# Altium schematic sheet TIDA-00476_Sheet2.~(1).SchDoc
size 431 x 279 mm; Date: Not shown in title block; ApprovedBy: Not shown in title block; CheckedBy: Not shown in title block; Author: Not shown in title block; CompanyName: Not shown in title block; DrawnBy: Salil Chellappan; Engineer: Not shown in title block; Organization: Not shown in title block; Address1: Not shown in title block; Address2: Not shown in title block; Address3: Not shown in title block; Address4: Not shown in title block; DocumentNumber: 2; Revision: Use project parameter SCH_Rev; SheetNumber: 2; SheetTotal: 3; PageSetup: Record=PageOptions¦CenterHorizontal=True¦CenterVertical=True¦PrintScale=0.64¦XCorrection=1.00¦YCorrection=1.00¦PrintKind=0¦BorderSize=5000000¦LeftOffset=0¦BottomOffset=0¦Orientation=2¦PaperLength=1000¦PaperWidth=1000¦Scale=100¦PaperSource=15¦PrintQuality=600¦MediaType=1¦DitherType=10¦PrintScaleMode=1¦PaperKind=Letter
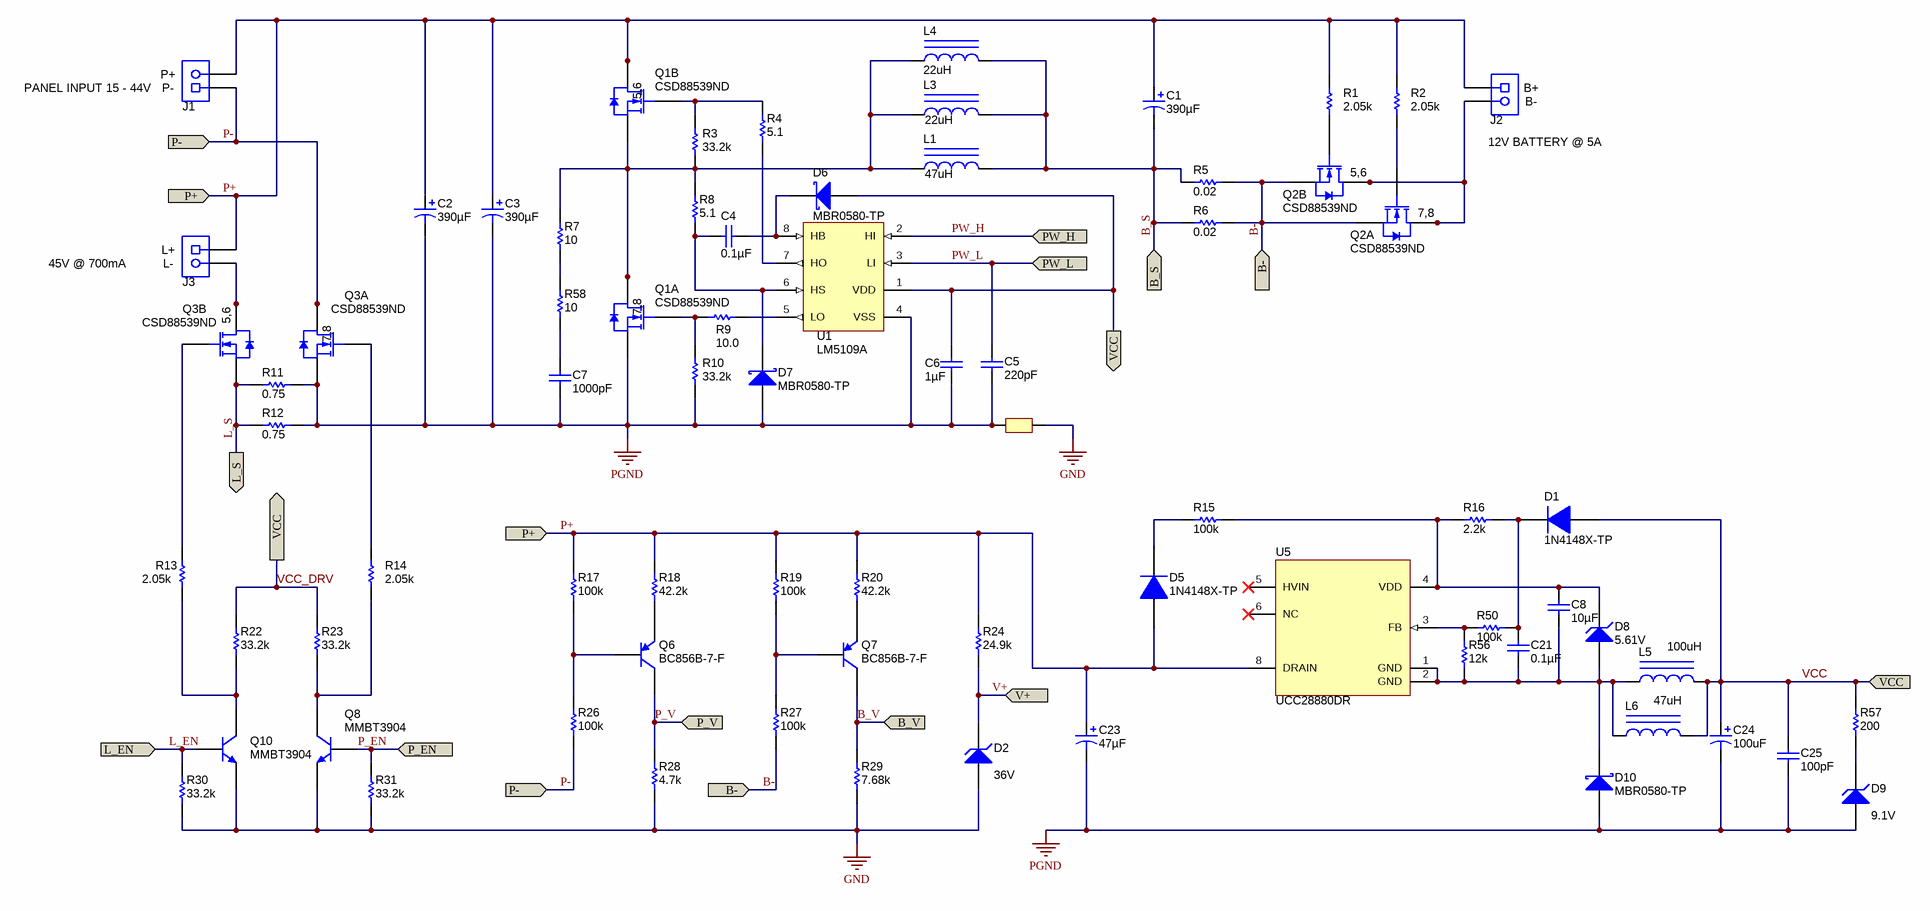
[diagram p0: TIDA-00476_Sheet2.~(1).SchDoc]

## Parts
C1  ValueDisplayed: 390µF  [KZN_1000x2000]  (hidden comment: EKYB630ELL391MJ30S)
C2  ValueDisplayed: 390µF  [KZN_1000x2000]  (hidden comment: EKYB630ELL391MJ30S)
C3  ValueDisplayed: 390µF  [KZN_1000x2000]  (hidden comment: EKYB630ELL391MJ30S)
C4  ValueDisplayed: 0.1µF  [0805_HV]  (hidden comment: 08053C104KAT2A)
C5  ValueDisplayed: 220pF  [0805_HV]  (hidden comment: GRM2165C2A221JA01D)
C6  ValueDisplayed: 1µF  [0805_HV]  (hidden comment: 08055C105KAT2A)
C7  ValueDisplayed: 1000pF  [0805_HV]  (hidden comment: GRM2195C2A102JA01D)
C8  ValueDisplayed: 10µF  [0603]  (hidden comment: C1608X5R1A106M)
C21  ValueDisplayed: 0.1µF  [0603]  (hidden comment: 0603YC104JAT2A)
C23  ValueDisplayed: 47µF  [ZLJ_500x1100]  (hidden comment: 35ZLJ47MTA5X11)
C24  ValueDisplayed: 100uF  [ZLJ_500x1100]  (hidden comment: 16PX100MEFCTA5X11)
C25  ValueDisplayed: 100pF  [0603]  (hidden comment: 06033C101KAT2A)
D1  1N4148X-TP  [SOD-523]
D2  value 36V  [SOD-123]  (hidden comment: MMSZ4715-V)
D5  1N4148X-TP  [SOD-523]
D6  MBR0580-TP  [SOD-123]
D7  MBR0580-TP  [SOD-123]
D8  5.61V  [SOD-523]
D9  value 9.1V  [SOD-123]  (hidden comment: MMSZ4696-V)
D10  MBR0580-TP  [SOD-123]
J1  282841-2  [TEC_282841-2]  (value not drawn)
J2  282841-2  [TEC_282841-2]  (value not drawn)
J3  282841-2  [TEC_282841-2]  (value not drawn)
L1  value 47uH  [WE-HCB_1890]  (hidden comment: 74435574700)
L3  value 22uH  [mss1278]  (hidden comment: MSS1278-223MLB)
L4  22uH  [WE-HCB_1890]
L5  100uH  [SRN3015]
L6  47uH  [SRN3015]
NT1  Net-Tie  [Net-Tie_20milWide_60milLong]  (value not drawn)  (net tie, no BOM)
Q1  CSD88539ND  [SO-8L]  (parts A,B of 2)
Q2  CSD88539ND  [SO-8L]  (parts A,B of 2)
Q3  CSD88539ND  [SO-8L]  (parts A,B of 2)
Q6  BC856B-7-F  [SOT-23]
Q7  BC856B-7-F  [SOT-23]
Q8  MMBT3904  [SOT-23L]
Q10  MMBT3904  [SOT-23L]
R1  value 2.05k  [0805_HV]  (hidden comment: CRCW08052K05FKEA)
R2  value 2.05k  [0805_HV]  (hidden comment: CRCW08052K05FKEA)
R3  value 33.2k  [0805_HV]  (hidden comment: CRCW080533K2FKEA)
R4  ValueDisplayed: 5.1  [0805_HV]  (hidden comment: RC0805JR-075R1L)
R5  ValueDisplayed: 0.02  [1206]  (hidden comment: CSR1206FK20L0)
R6  ValueDisplayed: 0.02  [1206]  (hidden comment: CSR1206FK20L0)
R7  ValueDisplayed: 10  [1206]  (hidden comment: CRCW120610R0JNEA)
R8  ValueDisplayed: 5.1  [0603]  (hidden comment: CRCW06035R10JNEA)
R9  value 10.0  [0805_HV]  (hidden comment: CRCW080510R0FKEA)
R10  value 33.2k  [0805_HV]  (hidden comment: CRCW080533K2FKEA)
R11  ValueDisplayed: 0.75  [1206]  (hidden comment: CSR1206FKR750)
R12  ValueDisplayed: 0.75  [1206]  (hidden comment: CSR1206FKR750)
R13  value 2.05k  [0805_HV]  (hidden comment: CRCW08052K05FKEA)
R14  value 2.05k  [0805_HV]  (hidden comment: CRCW08052K05FKEA)
R15  ValueDisplayed: 100k  [0603]  (hidden comment: CRCW0603100KJNEA)
R16  ValueDisplayed: 2.2k  [0603]  (hidden comment: CRCW06032K20JNEA)
R17  value 100k  [0805_HV]  (hidden comment: CRCW0805100KFKEA)
R18  ValueDisplayed: 42.2k  [0805_HV]  (hidden comment: CRCW080542K2FKEA)
R19  value 100k  [0805_HV]  (hidden comment: CRCW0805100KFKEA)
R20  ValueDisplayed: 42.2k  [0805_HV]  (hidden comment: CRCW080542K2FKEA)
R22  value 33.2k  [0805_HV]  (hidden comment: CRCW080533K2FKEA)
R23  value 33.2k  [0805_HV]  (hidden comment: CRCW080533K2FKEA)
R24  ValueDisplayed: 24.9k  [0805_HV]  (hidden comment: ERJ-6ENF2492V)
R26  value 100k  [0805_HV]  (hidden comment: CRCW0805100KFKEA)
R27  value 100k  [0805_HV]  (hidden comment: CRCW0805100KFKEA)
R28  ValueDisplayed: 4.7k  [0805_HV]  (hidden comment: CRCW08054K70JNEA)
R29  ValueDisplayed: 7.68k  [0805_HV]  (hidden comment: CRCW08057K68FKEA)
R30  value 33.2k  [0805_HV]  (hidden comment: CRCW080533K2FKEA)
R31  value 33.2k  [0805_HV]  (hidden comment: CRCW080533K2FKEA)
R50  ValueDisplayed: 100k  [0603]  (hidden comment: CRCW0603100KJNEA)
R56  ValueDisplayed: 12k  [0603]  (hidden comment: CRCW060312K0JNEA)
R57  ValueDisplayed: 200  [0603]  (hidden comment: CRCW0603200RJNEA)
R58  ValueDisplayed: 10  [1206]  (hidden comment: CRCW120610R0JNEA)
U1  LM5109A  [M08A_N]
U5  UCC28880DR  [D0007A_N]

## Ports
B- (in), B_S (in), B_V (in), L_EN (in), L_S (out), P+ (in), P- (in), P_EN (in), P_V (in), PW_H, PW_L, V+, VCC

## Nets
GND: D2.2(A) NT1.1 Q8.2(E) Q10.2(E) R28.1 R29.1 R30.1 R31.1
PGND: C2.2(-) C3.2(-) C5.2 C6.2 C7.2 C23.2(-) C24.2(-) C25.2 D7.2(A) D9.2(A) D10.2(A) NT1.2 Q1.1(S) Q3.1(S) R10.1 R11.2 R12.2 U1.4(VSS)
B-: Q2.1(S) Q2.3(S) R5.2 R6.2 R27.1 ; port B-
B_S: C1.2(-) L1.2 L3.2 L4.2 R5.1 R6.1 ; port B_S
B_V: Q7.3(C) R29.2 ; port B_V
L_EN: Q10.1(B) R30.2 ; port L_EN
L_S: Q3.3(S) R11.1 R12.1 ; port L_S
P+: C1.1(+) C2.1(+) C3.1(+) C23.1(+) D5.2(A) J1.2 J2.1 J3.1 Q1.5(D) Q1.6(D) R1.2 R2.2 R17.2 R18.2 R19.2 R20.2 R24.2 U5.8(DRAIN) ; port P+
P-: J1.1 Q3.7(D) Q3.8(D) R26.1 ; port P-
P_EN: Q8.1(B) R31.2 ; port P_EN
P_V: Q6.3(C) R28.2 ; port P_V
PW_H: U1.2(HI) ; port PW_H
PW_L: C5.1 U1.3(LI) ; port PW_L
V+: D2.1(K) R24.1 ; port V+
VCC: C6.1 C24.1(+) C25.1 D1.2(A) D6.2(A) L5.2 L6.2 R22.2 R23.2 R57.2 U1.1(VDD) ; port VCC  [also labelled VCC_DRV]
NetC4_1: C4.1 D6.1(K) U1.8(HB)
NetC4_2: C4.2 D7.1(K) R8.1 U1.6(HS)
NetC7_1: C7.1 R58.1
NetC8_1: C8.1 D8.1(K) R15.1 R16.1 U5.4(VDD)
NetC8_2: C8.2 C21.2 D8.2(A) D10.1(K) L5.1 L6.1 R56.1 U5.1(GND) U5.2(GND)
NetC21_1: C21.1 D1.1(K) R16.2 R50.1
NetD5_1: D5.1(K) R15.2
NetD9_1: D9.1(K) R57.1
NetJ2_2: J2.2 Q2.5(D) Q2.6(D) Q2.7(D) Q2.8(D)
NetJ3_2: J3.2 Q3.5(D) Q3.6(D)
NetL1_1: L1.1 L3.1 L4.1 Q1.3(S) Q1.7(D) Q1.8(D) R3.1 R7.2 R8.2
NetQ1_2: Q1.2(G) R9.1 R10.2
NetQ1_4: Q1.4(G) R3.2 R4.2
NetQ2_2: Q2.2(G) R2.1
NetQ2_4: Q2.4(G) R1.1
NetQ3_2: Q3.2(G) R14.2
NetQ3_4: Q3.4(G) R13.2
NetQ6_1: Q6.1(B) R17.1 R26.2
NetQ6_2: Q6.2(E) R18.1
NetQ7_1: Q7.1(B) R19.1 R27.2
NetQ7_2: Q7.2(E) R20.1
NetQ8_3: Q8.3(C) R14.1 R23.1
NetQ10_3: Q10.3(C) R13.1 R22.1
NetR4_1: R4.1 U1.7(HO)
NetR7_1: R7.1 R58.2
NetR9_2: R9.2 U1.5(LO)
NetR50_2: R50.2 R56.2 U5.3(FB)

Not connected (* = marked no-connect by the designer): U5 5(HVIN)* 6(NC)*

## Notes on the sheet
- PANEL INPUT 15 - 44V
- (near J1) P+
- (near J1) P-
- (near J2) B-
- (near J2) B+
- (near J2) 12V BATTERY @ 5A
- 45V @ 700mA
- (near J3) L-
- (near J3) L+

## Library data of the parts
C1 = EKZN350ELL471MJ20S: CAP, AL,390 µF, 63 V, +/- 20%, 0.043 ohm, TH; Manufacturer: Chemi-Con; Polarized: Y; CompType: Capacitor; Value: 390uF; U/M: EA; Cap_F: 0.00039; Tolerance_%: 20; Value1: 0.04 ohm; VDC_V: 63; Value2: 63V; ESR_ohm: 0.04; IRMS_A: 1.78; TaMin_C: -40; TaMax_C: 105; Cap_Case: 10x30mm
C2 C3 = EKZN350ELL471MJ20S: CAP, AL, 470 µF, 35 V, +/- 20%, 0.028 ohm, TH; Manufacturer: Chemi-Con; Polarized: Y; CompType: Capacitor; Value: 390uF; U/M: EA; Cap_F: 0.00039; Tolerance_%: 20; Value1: 0.04 ohm; VDC_V: 63; Value2: 63V; ESR_ohm: 0.04; IRMS_A: 1.78; TaMin_C: -40; TaMax_C: 105; Cap_Case: 10x30mm
C4 = 08053C104KAT2A: CAP, CERM, 0.1uF, 25V, +/-10%, X7R, 0805; Manufacturer: AVX; Polarized: N; CompType: Capacitor; U/M: EA; Cap_F: 0.0000001; Tolerance_%: 10; ESR_Ohm: 0.28; Value1: 0.28 ohm; VDC_V: 25; TaMin_C: -55; TaMax_C: 125; Cap_Case: 0805
C5 = GRM2165C2A221JA01D: CAP, CERM, 220 pF, 100 V, +/- 5%, C0G/NP0, 0805; Manufacturer: MuRata; Polarized: N; CompType: Capacitor; Value: 220pF; U/M: EA; Cap_F: 0.00000000022; Tolerance_%: 5; Value1: Unknown; VDC_V: 100; Value2: 100V; TaMin_C: -55; TaMax_C: 125; Cap_Case: 0805
C6 = 08055C105KAT2A: CAP, CERM, 1uF, 50V, +/-10%, X7R, 0805; Manufacturer: AVX; Polarized: N; CompType: Capacitor; U/M: EA; Cap_F: 0.000001; Tolerance_%: 10; Value1: Unknown; VDC_V: 50; TaMin_C: -55; TaMax_C: 125; Cap_Case: 0805
C7 = GRM2195C2A102JA01D: CAP, CERM, 1000 pF, 100 V, +/- 5%, C0G/NP0, 0805; Manufacturer: MuRata; Polarized: N; CompType: Capacitor; Value: 1000pF; U/M: EA; Cap_F: 0.000000001; Tolerance_%: 5; Value1: Unknown; VDC_V: 100; Value2: 100V; TaMin_C: -55; TaMax_C: 125; Cap_Case: 0805
C8 = C1608X5R1A106M: CAP, CERM, 10 µF, 10 V, +/- 20%, X5R, 0603; Manufacturer: TDK; Polarized: N; CompType: Capacitor; Value: 10uF; U/M: EA; Cap_F: 0.00001; Tolerance_%: 20; ESR_ohm: 0.0078; Value1: 0.0078 ohm; VDC_V: 10; Value2: 10V; IRMS_A: 1.85; TaMin_C: -55; TaMax_C: 85
C21 = 0603YC104JAT2A: CAP, CERM, 0.1 µF, 16 V, +/- 5%, X7R, 0603; Manufacturer: AVX; Polarized: N; CompType: Capacitor; Value: 0.1uF; U/M: EA; Cap_F: 0.0000001; Tolerance_%: 5; ESR_ohm: 0.039; Value1: 0.039 ohm; VDC_V: 16; Value2: 16V; TaMin_C: -55; TaMax_C: 125
C23 = 35ZLJ47MTA5X11: CAP, AL, 47 µF, 35 V, +/- 20%, 0.4 ohm, TH; Manufacturer: Rubycon; Polarized: Y; CompType: Capacitor; Value: 47uF; U/M: EA; Cap_F: 0.000047; Tolerance_%: 20; Value1: 0.4 ohm; VDC_V: 35; Value2: 35V; ESR_ohm: 0.4; IRMS_A: 0.45; TaMin_C: -40; TaMax_C: 105; Cap_Case: 5x11mm
C24 = 35ZLJ47MTA5X11: CAP, AL, 100 µF, 16 V, +/- 20%, 0.4 ohm, TH; Manufacturer: Rubycon; Polarized: Y; CompType: Capacitor; Value: 100uF; U/M: EA; Cap_F: 0.000047; Tolerance_%: 20; Value1: 0.4 ohm; VDC_V: 16; Value2: 16V; ESR_ohm: 0.4; IRMS_A: 0.45; TaMin_C: -40; TaMax_C: 105; Cap_Case: 5x11mm
C25 = 06033C101KAT2A: CAP, CERM, 100 pF, 25 V, +/- 10%, X7R, 0603; Manufacturer: AVX; Polarized: N; CompType: Capacitor; Value: 100pF; U/M: EA; Cap_F: 0.0000000001; Tolerance_%: 10; Value1: Unknown; VDC_V: 25; Value2: 25V; TaMin_C: -55; TaMax_C: 125
D1 D5 = 1N4148X-TP: Diode, Switching, 75 V, 0.3 A, SOD-523; Manufacturer: Micro Commercial Components; U/M: EA; Vf_V: 1.25; Value: 75V; Value1: 0.3A; Value2: 1.25V; Io_A: 0.3; Vr_V: 75; TJmax_C: 150
D2 = MMSZ4715-V: Diode, Zener, 36 V, 500 mW, SOD-123; Manufacturer: Vishay-Semiconductor; SymbolCreator: a0412235; U/M: EA; Power_W: 0.5; Vz_V: 36; Value1: 0.5W; RJA_CperW: 67
D6 D7 D10 = MBR0580-TP: Diode, Schottky, 80 V, 0.5 A, SOD-123; Manufacturer: Micro Commercial Components; U/M: EA; Vf_V: 0.8; Value: 80V; Value1: 0.5A; Value2: 0.8V; Io_A: 0.5; Vr_V: 80; TJmax_C: 150
D8 = MM5Z5V6ST1G: Diode, Zener, 5.61 V, 500 mW, SOD-523; Manufacturer: ON Semiconductor; SymbolCreator: a0412235; U/M: EA; Power_W: 0.5; Vz_V: 5.61; Value1: 0.5W; RJA_CperW: 250
D9 = MMSZ4696-V: Diode, Zener, 9.1 V, 500 mW, SOD-123; Manufacturer: Vishay-Semiconductor; SymbolCreator: a0412235; U/M: EA; Power_W: 0.5; Vz_V: 9.1; Value1: 0.5W; RJA_CperW: 67
J1-J3 = 282841-2: Terminal Block, 2x1, 5.08mm, TH; Manufacturer: TE Connectivity; SymbolCreator: a0412235; U/M: EA
L1 = 74435574700: Inductor, Shielded Drum Core, Ferrite, 47 µH, 6.8 A, 0.0335 ohm, SMD; Manufacturer: Wurth Elektronik; Ind_H: 47.0E-6; ValueDisplayed: 47µH; Imax_A: 6.8; Irms: 6.8A @ 50C rise; Isat: 7A @ 30% inductance drop; DCR_ohm: 0.0335; Value2: 6.8A
L3 = MSS1278-223MLB: Inductor, Shielded Drum Core, Ferrite, 22 µH, 4 A, 0.04 ohm, SMD; Manufacturer: Coilcraft; Ind_H: 22.0E-6; ValueDisplayed: 22µH; Imax_A: 4; Irms: 4A @ 40C rise; Isat: 7.24A @ 30% inductance drop; DCR_ohm: 0.04; Value2: 4A
L4 = 74435572200: Inductor, Shielded Drum Core, Ferrite, 22 µH, 11 A, 0.0146 ohm, SMD; Manufacturer: Wurth Elektronik; Ind_H: 22.0E-6; ValueDisplayed: 22µH; Imax_A: 11; Irms: 11A @ 50C rise; Isat: 11A @ 30% inductance drop; DCR_ohm: 0.0146; Value2: 11A
L5 = SRN3015-1R0Y: Inductor, Drum Core, Ferrite, 100 µH, 0.4 A, 1.596 ohm, SMD; PartNumber: SRN4018-101M; Manufacturer: Bourns; Ind_H: 1.0E-4; ValueDisplayed: 100µH; Imax_A: 0.4; DCR_ohm: 0.048; Value2: 0.4A
L6 = SRN3015-1R0Y: Inductor, Drum Core, Ferrite, 47 µH, 0.4 A, 1.4 ohm, SMD; PartNumber: SRN3015-470M; Manufacturer: Bourns; Ind_H: 47E-6; Imax_A: 2.35; DCR_ohm: 0.048; Value1: 1.4Ohm; Value2: 0.4A
NT1 = Net-Tie: Single point connection between nets.; SymbolCreator: codlsc
Q1-Q3 = CSD88539ND: MOSFET, N-CH, 60V, 6.3A, SO-8; Manufacturer: Texas Instruments; Alternate Manufacturer: None; U/M: EA; ChType: N; VdsMax_V: 60; Value1: ? ohm; Value2: 7.2 nC; QgTyp_nC: 7.2; Vgs_V: 20; IdsMax_A: 6.3
Q6 Q7 = BC856B-7-F, Diodes Inc.: Transistor, PNP, 65 V, 0.1 A, SOT-23; CompType: BJT; PNP: 1; NPN: 0; Vceo_V: 65; Vcesat1_V: 0.075; Value: 65 V; IcRated_A: 0.1; Value1: 0.1 A; HfeMax: 330; TaMin_C: -65; TaMax_C: 150; U/M: EA
Q8 Q10 = MMBT3904, Fairchild Semiconductor: Transistor, NPN, 40V, 0.2A, SOT-23; CompType: BJT; PNP: 0; NPN: 1; Vceo_V: 40; Vcesat1_V: 0.2; Value: 0.2V; HfeMax: 300; TaMin_C: -55; TaMax_C: 150; U/M: EA
R1 R2 R13 R14 = CRCW08052K05FKEA: RES, 2.05k ohm, 1%, 0.125W, 0805; Manufacturer: Vishay-Dale; CompType: Resistor; Res_ohm: 2050; Value_Code: 2k05; Tolerance_%: 1; Power_W: 0.125; VDC_V: 150; TempCo: 100 ppm/C; EIA_Code: E96; U/M: EA
R3 R10 R22 R23 R30 R31 = CRCW080533K2FKEA: RES, 33.2k ohm, 1%, 0.125W, 0805; Manufacturer: Vishay-Dale; CompType: Resistor; Res_ohm: 33200; Value_Code: 33k2; Tolerance_%: 1; Power_W: 0.125; VDC_V: 150; TempCo: 100 ppm/C; EIA_Code: E96; U/M: EA
R4 = RC0805JR-075R1L: RES, 5.1, 5%, 0.125 W, 0805; Manufacturer: Yageo America; CompType: Resistor; Value: 5.1; Value_Code: 5R10; Tolerance_%: 5; Power_W: 0.125; Value2: 0.125W; VDC_V: 150; TempCo: 200 ppm/C; EIA_Code: E24; U/M: EA
R5 R6 = CSR1206FK20L0: RES, 0.02, 1%, 0.5 W, 1206; Manufacturer: Stackpole Electronics Inc; CompType: Resistor; Value: 0.02; Value_Code: R020; Tolerance_%: 1; Power_W: 0.5; Value2: 0.5W; TempCo: 100 ppm/C; EIA_Code: E96; U/M: EA
R7 R58 = CRCW120610R0JNEA: RES, 10, 5%, 0.25 W, 1206; Manufacturer: Vishay-Dale; CompType: Resistor; Value: 10; Value_Code: 10R0; Tolerance_%: 5; Power_W: 0.25; Value2: 0.25W; VDC_V: 200; TempCo: 200 ppm/C; EIA_Code: E24; U/M: EA
R8 = CRCW06035R10JNEA: RES, 5.1, 5%, 0.1 W, 0603; Manufacturer: Vishay-Dale; CompType: Resistor; Value: 5.1; Value_Code: 5R10; Tolerance_%: 5; Power_W: 0.1; Value2: 0.1W; VDC_V: 75; TempCo: 200 ppm/C; EIA_Code: E24; U/M: EA
R9 = CRCW080510R0FKEA: RES, 10.0 ohm, 1%, 0.125W, 0805; Manufacturer: Vishay-Dale; CompType: Resistor; Res_ohm: 10; Value_Code: 10R0; Tolerance_%: 1; Power_W: 0.125; VDC_V: 150; TempCo: 100 ppm/C; EIA_Code: E96; U/M: EA
R11 R12 = CSR1206FKR750: RES, 0.75, 1%, 0.5 W, 1206; Manufacturer: Stackpole Electronics Inc; CompType: Resistor; Value: 0.75; Value_Code: R750; Tolerance_%: 1; Power_W: 0.5; Value2: 0.5W; TempCo: 100 ppm/C; EIA_Code: E96; U/M: EA
R15 R50 = CRCW0603100KJNEA: RES, 100 k, 5%, 0.1 W, 0603; Manufacturer: Vishay-Dale; CompType: Resistor; Value: 100k; Res_ohm: 100000; Tolerance_%: 5; Power_W: 0.1; Value2: 0.1W; VDC_V: 75; TempCo: 200 ppm/C; EIA_Code: E24; U/M: EA
R16 = CRCW06032K20JNEA: RES, 2.2 k, 5%, 0.1 W, 0603; Manufacturer: Vishay-Dale; CompType: Resistor; Value: 2.2k; Res_ohm: 2200; Value_Code: 2k20; Tolerance_%: 5; Power_W: 0.1; Value2: 0.1W; VDC_V: 75; TempCo: 200 ppm/C; EIA_Code: E24; U/M: EA
R17 R19 R26 R27 = CRCW0805100KFKEA: RES, 100k ohm, 1%, 0.125W, 0805; Manufacturer: Vishay-Dale; CompType: Resistor; Res_ohm: 100000; Tolerance_%: 1; Power_W: 0.125; VDC_V: 150; TempCo: 100 ppm/C; EIA_Code: E96; U/M: EA
R18 R20 = CRCW080542K2FKEA: RES, 42.2 k, 1%, 0.125 W, 0805; Manufacturer: Vishay-Dale; CompType: Resistor; Value: 42.2k; Res_ohm: 42200; Value_Code: 42k2; Tolerance_%: 1; Power_W: 0.125; Value2: 0.125W; VDC_V: 150; TempCo: 100 ppm/C; EIA_Code: E96; U/M: EA
R24 = ERJ-6ENF2492V: RES, 24.9 k, 1%, 0.125 W, 0805; Manufacturer: Panasonic; CompType: Resistor; Value: 24.9k; Res_ohm: 24900; Value_Code: 24k9; Tolerance_%: 1; Power_W: 0.125; Value2: 0.125W; TempCo: 100 ppm/C; EIA_Code: E96; U/M: EA
R28 = CRCW08054K70JNEA: RES, 4.7 k, 5%, 0.125 W, 0805; Manufacturer: Vishay-Dale; CompType: Resistor; Value: 4.7k; Res_ohm: 4700; Value_Code: 4k70; Tolerance_%: 5; Power_W: 0.125; Value2: 0.125W; VDC_V: 150; TempCo: 200 ppm/C; EIA_Code: E24; U/M: EA
R29 = CRCW08057K68FKEA: RES, 7.68 k, 1%, 0.125 W, 0805; Manufacturer: Vishay-Dale; CompType: Resistor; Value: 7.68k; Res_ohm: 7680; Value_Code: 7k68; Tolerance_%: 1; Power_W: 0.125; Value2: 0.125W; VDC_V: 150; TempCo: 100 ppm/C; EIA_Code: E96; U/M: EA
R56 = CRCW060312K0JNEA: RES, 12 k, 5%, 0.1 W, 0603; Manufacturer: Vishay-Dale; CompType: Resistor; Value: 12k; Res_ohm: 12000; Value_Code: 12k0; Tolerance_%: 5; Power_W: 0.1; Value2: 0.1W; VDC_V: 75; TempCo: 200 ppm/C; EIA_Code: E24; U/M: EA
R57 = CRCW0603200RJNEA: RES, 200, 5%, 0.1 W, 0603; Manufacturer: Vishay-Dale; CompType: Resistor; Value: 200; Value_Code: 200R; Tolerance_%: 5; Power_W: 0.1; Value2: 0.1W; VDC_V: 75; TempCo: 200 ppm/C; EIA_Code: E24; U/M: EA
U1 = LM5109AMAX/NOPB: High Voltage 1A Peak Half Bridge Gate Driver, 8-pin Narrow SOIC, Pb-Free; Manufacturer: Texas Instruments; PackageTopMarking: NSZXTT*L5109*AMA; PowerWise: N; CompType: MiscPower
U5 = UCC28880DR: 700-V Lowest Quiescent Current Off-Line Switcher, D0007A; Manufacturer: Texas Instruments; SymbolCreator: a0411947; CompType: IC; U/M: EA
